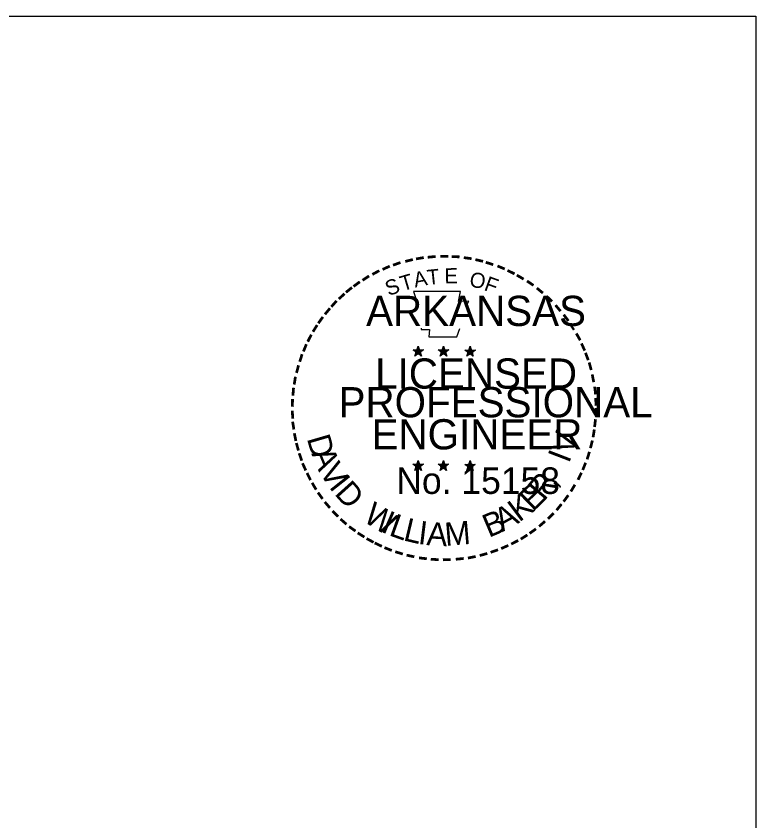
# Model space of a CAD drawing. Extents: x 28704 to 32542, y 50360 to 59122.
# Drawn here: x 30170 to 30422.7, y 58847.3 to 59122.4 of the extents above; entities that cross this region are included whole.
import ezdxf

# ---------------------------------------------------------------- set-up
doc = ezdxf.new("R2010")
doc.units = 0
doc.layers.add('R_Border Prem', color=7, linetype='Continuous')
doc.layers.add('R_Contours', color=7, linetype='Continuous')

msp = doc.modelspace()

# ---------------------------------------------------------------- linework, layer by layer
at = {"layer": 'R_Border Prem'}
for p, q in [((30305.59, 59008.27), (30307.38, 59007.7)), ((30305.59, 59008.27), (30306.89, 59008.04)), ((30305.59, 59008.27), (30306.81, 59007.64)), ((30307.38, 59009.58), (30307.17, 59008.28)), ((30307.38, 59007.7), (30307.38, 59009.58)), ((30307.38, 59009.58), (30307.64, 59008.29)), ((30309.17, 59008.27), (30307.38, 59007.7)), ((30309.17, 59008.27), (30307.7, 59008.02)), ((30309.17, 59008.27), (30308.12, 59007.74)), ((30314.2, 59008.27), (30316, 59007.7)), ((30314.2, 59008.27), (30315.5, 59008.04)), ((30314.2, 59008.27), (30315.42, 59007.64)), ((30316, 59009.58), (30315.78, 59008.28)), ((30316, 59007.7), (30316, 59009.58)), ((30316, 59009.58), (30316.25, 59008.29)), ((30317.79, 59008.27), (30316, 59007.7)), ((30317.79, 59008.27), (30316.31, 59008.02)), ((30317.79, 59008.27), (30316.73, 59007.74)), ((30323.29, 59008.21), (30325.09, 59007.63)), ((30323.29, 59008.21), (30324.6, 59007.97)), ((30323.29, 59008.21), (30324.51, 59007.58)), ((30325.09, 59009.52), (30324.88, 59008.22)), ((30325.09, 59007.63), (30325.09, 59009.52)), ((30325.09, 59009.52), (30325.34, 59008.23)), ((30326.88, 59008.21), (30325.09, 59007.63)), ((30326.88, 59008.21), (30325.41, 59007.95)), ((30326.88, 59008.21), (30325.83, 59007.68)), ((30306.27, 59006.16), (30307.38, 59007.7)), ((30306.27, 59006.16), (30306.92, 59007.42)), ((30306.27, 59006.16), (30307.37, 59007.28)), ((30308.48, 59006.16), (30307.37, 59007.27)), ((30308.48, 59006.16), (30307.38, 59007.7)), ((30308.48, 59006.16), (30307.78, 59007.66)), ((30314.88, 59006.16), (30316, 59007.7)), ((30314.88, 59006.16), (30315.53, 59007.42)), ((30314.88, 59006.16), (30315.99, 59007.28)), ((30317.09, 59006.16), (30315.99, 59007.27)), ((30317.09, 59006.16), (30316, 59007.7)), ((30317.09, 59006.16), (30316.39, 59007.66)), ((30323.98, 59006.1), (30325.09, 59007.63)), ((30323.98, 59006.1), (30324.63, 59007.36)), ((30323.98, 59006.1), (30325.08, 59007.22)), ((30326.19, 59006.1), (30325.08, 59007.21)), ((30326.19, 59006.1), (30325.09, 59007.63)), ((30326.19, 59006.1), (30325.48, 59007.6)), ((30307.36, 58970.53), (30307.15, 58969.23)), ((30307.36, 58968.65), (30307.36, 58970.53)), ((30307.36, 58970.53), (30307.62, 58969.24)), ((30315.97, 58970.53), (30315.76, 58969.23)), ((30315.97, 58968.65), (30315.97, 58970.53)), ((30315.97, 58970.53), (30316.22, 58969.24)), ((30325.08, 58970.48), (30324.87, 58969.18)), ((30325.08, 58968.6), (30325.08, 58970.48)), ((30325.08, 58970.48), (30325.33, 58969.19)), ((30305.56, 58969.22), (30307.36, 58968.65)), ((30305.56, 58969.22), (30306.87, 58968.99)), ((30305.56, 58969.22), (30306.79, 58968.59)), ((30306.25, 58967.12), (30307.36, 58968.65)), ((30306.25, 58967.12), (30306.9, 58968.37)), ((30306.25, 58967.12), (30307.35, 58968.24)), ((30308.46, 58967.12), (30307.35, 58968.22)), ((30309.15, 58969.22), (30307.36, 58968.65)), ((30308.46, 58967.12), (30307.36, 58968.65)), ((30309.15, 58969.22), (30307.68, 58968.97)), ((30308.46, 58967.12), (30307.76, 58968.62)), ((30309.15, 58969.22), (30308.1, 58968.69)), ((30314.17, 58969.22), (30315.97, 58968.65)), ((30314.17, 58969.22), (30315.48, 58968.99)), ((30314.17, 58969.22), (30315.39, 58968.59)), ((30314.86, 58967.12), (30315.97, 58968.65)), ((30314.86, 58967.12), (30315.51, 58968.37)), ((30314.86, 58967.12), (30315.96, 58968.24)), ((30317.07, 58967.12), (30315.96, 58968.22)), ((30317.76, 58969.22), (30315.97, 58968.65)), ((30317.07, 58967.12), (30315.97, 58968.65)), ((30317.76, 58969.22), (30316.28, 58968.97)), ((30317.07, 58967.12), (30316.36, 58968.62)), ((30317.76, 58969.22), (30316.71, 58968.69)), ((30323.28, 58969.17), (30325.08, 58968.6)), ((30323.28, 58969.17), (30324.59, 58968.94)), ((30323.28, 58969.17), (30324.5, 58968.54)), ((30323.97, 58967.06), (30325.08, 58968.6)), ((30323.97, 58967.06), (30324.62, 58968.32)), ((30323.97, 58967.06), (30325.07, 58968.18)), ((30326.18, 58967.06), (30325.07, 58968.17)), ((30326.87, 58969.17), (30325.08, 58968.6)), ((30326.18, 58967.06), (30325.08, 58968.6)), ((30326.87, 58969.17), (30325.4, 58968.92)), ((30326.18, 58967.06), (30325.47, 58968.57)), ((30326.87, 58969.17), (30325.82, 58968.64))]:
    msp.add_line(p, q, dxfattribs=at)
for points in [[(30305.8, 59028.26), (30307.18, 59024)], [(30323.9, 59023.51), (30324.63, 59024.97), (30321.1, 59024.85), (30321.86, 59028.26), (30305.8, 59028.26)], [(30308.33, 59015.77), (30308.33, 59015.32), (30311.24, 59015.22), (30310.96, 59012.79), (30320.6, 59012.79), (30321.64, 59015.55)], [(30307.38, 59009.58), (30308.48, 59006.16), (30305.59, 59008.27), (30309.17, 59008.27), (30306.27, 59006.16), (30307.38, 59009.58)], [(30316, 59009.58), (30317.09, 59006.16), (30314.2, 59008.27), (30317.79, 59008.27), (30314.88, 59006.16), (30316, 59009.58)], [(30325.09, 59009.52), (30326.19, 59006.1), (30323.29, 59008.21), (30326.88, 59008.21), (30323.98, 59006.1), (30325.09, 59009.52)], [(30307.36, 58970.53), (30308.46, 58967.12), (30305.56, 58969.22), (30309.15, 58969.22), (30306.25, 58967.12), (30307.36, 58970.53)], [(30315.97, 58970.53), (30317.07, 58967.12), (30314.17, 58969.22), (30317.76, 58969.22), (30314.86, 58967.12), (30315.97, 58970.53)], [(30325.08, 58970.48), (30326.18, 58967.06), (30323.28, 58969.17), (30326.87, 58969.17), (30323.97, 58967.06), (30325.08, 58970.48)]]:
    msp.add_lwpolyline(points, dxfattribs=at)
for centre, radius in [((30307.38, 59007.69), 0.888), ((30307.38, 59007.69), 0.745), ((30307.38, 59007.69), 0.597), ((30307.38, 59007.69), 0.511), ((30307.38, 59007.69), 0.385), ((30307.38, 59007.69), 0.255), ((30315.99, 59007.69), 0.888), ((30315.99, 59007.69), 0.745), ((30315.99, 59007.69), 0.597), ((30315.99, 59007.69), 0.511), ((30315.99, 59007.69), 0.385), ((30315.99, 59007.69), 0.255), ((30325.09, 59007.63), 0.888), ((30325.09, 59007.63), 0.745), ((30325.09, 59007.63), 0.597), ((30325.09, 59007.63), 0.511), ((30325.09, 59007.63), 0.385), ((30307.38, 59007.69), 0.153), ((30315.99, 59007.69), 0.153), ((30325.09, 59007.63), 0.255), ((30325.09, 59007.63), 0.153), ((30307.36, 58968.64), 0.888), ((30315.96, 58968.64), 0.888), ((30325.08, 58968.59), 0.888), ((30307.36, 58968.64), 0.745), ((30307.36, 58968.64), 0.597), ((30307.36, 58968.64), 0.511), ((30307.36, 58968.64), 0.385), ((30307.36, 58968.64), 0.255), ((30307.36, 58968.64), 0.153), ((30315.96, 58968.64), 0.745), ((30315.96, 58968.64), 0.597), ((30315.96, 58968.64), 0.511), ((30315.96, 58968.64), 0.385), ((30315.96, 58968.64), 0.255), ((30315.96, 58968.64), 0.153), ((30325.08, 58968.59), 0.745), ((30325.08, 58968.59), 0.597), ((30325.08, 58968.59), 0.511), ((30325.08, 58968.59), 0.385), ((30325.08, 58968.59), 0.255), ((30325.08, 58968.59), 0.153)]:
    msp.add_circle(centre, radius, dxfattribs=at)
at = {"layer": 'R_Contours'}
msp.add_line((28703.96, 59122.36), (30422.71, 59122.36), dxfattribs=at)
msp.add_lwpolyline([(28703.92, 59122.36), (30422.71, 59122.36), (30422.71, 58022.33), (28703.92, 58022.33)], close=True, dxfattribs=at)

# ---------------------------------------------------------------- texts
at = {"layer": 'R_Border Prem'}
for s, height, rotation, p in [('-', 8.25, 19.1761, (30299.34, 59034.08)), ('-', 8.25, 13.6302, (30303.21, 59035.32)), ('-', 8.25, 10.2193, (30306.7, 59036.15)), ('-', 8.25, 5.8968, (30310.46, 59036.72)), ('-', 8.25, 0.1862, (30314.44, 59037.09)), ('-', 8.25, 357.743, (30318.17, 59037.02)), ('-', 8.25, 352.1617, (30322.01, 59036.74)), ('-', 8.25, 347.2049, (30325.71, 59036.15)), ('-', 8.25, 342.3362, (30328.99, 59035.35)), ('-', 8.25, 28.7918, (30292.81, 59031.05)), ('-', 8.25, 24.3072, (30296.07, 59032.69)), ('T', 5.16, 6.0228, (30310.66, 59030.46)), ('E', 5.16, 0.8323, (30316.36, 59031.03)), ('-', 8.25, 337.8551, (30332.78, 59034.2)), ('-', 8.25, 334.1211, (30336.03, 59032.8)), ('-', 8.25, 34.0636, (30289.73, 59029.15)), ('T', 5.16, 16.4036, (30302.03, 59028.31)), ('A', 5.16, 11.2132, (30306.29, 59029.6)), ('O', 5.16, 350.4515, (30324.63, 59029.95)), ('F', 5.16, 340.0707, (30329.55, 59028.77)), ('-', 8.25, 329.6409, (30339.02, 59031.34)), ('-', 8.25, 38.9507, (30284.29, 59025.16)), ('-', 8.25, 36.2317, (30286.75, 59027.11)), ('S', 5.16, 21.594, (30297.31, 59026.6)), ('-', 8.25, 325.8627, (30342.33, 59029.48)), ('-', 8.25, 42.9622, (30282.06, 59023.01)), ('-', 8.25, 320.5297, (30345.48, 59027.28)), ('-', 8.25, 48.4231, (30279.75, 59020.55)), ('-', 8.25, 315.5786, (30348.57, 59024.77)), ('-', 8.25, 50.6142, (30277.67, 59018.04)), ('-', 8.25, 309.8797, (30351.5, 59021.93)), ('-', 8.25, 54.2325, (30275.54, 59015.12)), ('-', 8.25, 306.6522, (30354.21, 59018.83)), ('-', 8.25, 58.0706, (30273.87, 59012.4)), ('-', 7.22, 303.6753, (30356.71, 59015.9)), ('-', 8.25, 62.8713, (30272.25, 59009.23)), ('-', 8.25, 299.6684, (30358.36, 59012.77)), ('-', 8.25, 294.6628, (30360.03, 59009.61)), ('-', 8.25, 67.7743, (30270.92, 59006.08)), ('-', 8.25, 72.3945, (30269.79, 59002.83)), ('-', 8.25, 290.5728, (30361.35, 59006.64)), ('-', 8.25, 75.461, (30268.77, 58999.15)), ('-', 8.25, 285.1233, (30362.56, 59003.65)), ('-', 8.25, 280.5493, (30363.59, 58999.82)), ('-', 8.25, 81.2013, (30268.09, 58995.48)), ('-', 8.25, 85.1863, (30267.7, 58991.91)), ('-', 8.25, 276.5962, (30364.43, 58995.86)), ('-', 8.25, 89.0622, (30267.57, 58988.3)), ('-', 8.25, 274.3301, (30364.74, 58992.14)), ('-', 8.25, 94.1959, (30267.75, 58984.56)), ('-', 8.25, 269.9407, (30364.91, 58988.88)), ('-', 8.25, 98.9479, (30268.12, 58981.12)), ('-', 8.25, 263.5172, (30364.81, 58985.45)), ('V', 7.94, 72.6573, (30359.99, 58972.07)), ('-', 8.25, 260.9953, (30364.45, 58982.07)), ('-', 8.25, 101.7149, (30268.82, 58977.34)), ('D', 7.94, 286.2848, (30269.28, 58978.05)), ('-', 8.25, 105.4578, (30269.66, 58974.27)), ('-', 8.25, 255.7626, (30363.88, 58978.58)), ('-', 8.25, 109.0874, (30270.76, 58971.02)), ('A', 7.94, 292.7835, (30270.79, 58972.89)), ('I', 7.94, 69.0301, (30358.84, 58969.29)), ('-', 8.25, 252.8681, (30362.95, 58974.87)), ('-', 8.25, 114.0643, (30272.07, 58967.95)), ('V', 7.94, 300.7936, (30273.44, 58966.81)), ('-', 8.25, 247.8887, (30361.8, 58971.4)), ('-', 8.25, 115.7289, (30273.65, 58964.76)), ('I', 7.94, 308.3502, (30276.69, 58961.46)), ('R', 7.94, 50.3651, (30350.33, 58956.46)), ('-', 8.25, 244.6197, (30360.45, 58968.15)), ('-', 8.25, 120.4471, (30275.49, 58961.74)), ('D', 7.94, 311.9774, (30278.5, 58959.06)), ('E', 7.94, 44.0175, (30346.55, 58952.81)), (',', 7.94, 57.4684, (30354.06, 58961.01)), ('-', 8.25, 239.0712, (30358.42, 58964.28)), ('-', 8.25, 125.8934, (30277.57, 58958.85)), ('K', 7.94, 36.9143, (30341.86, 58949.25)), ('-', 8.25, 233.8452, (30356.34, 58960.91)), ('-', 8.25, 130.7181, (30279.95, 58956)), ('W', 7.94, 328.0731, (30288.18, 58949.95)), ('-', 8.25, 231.2538, (30354.13, 58957.99)), ('-', 8.25, 134.2238, (30282.61, 58953.19)), ('I', 7.94, 336.6877, (30294.31, 58946.29)), ('B', 7.94, 22.8589, (30331.48, 58944.04)), ('A', 7.94, 28.9042, (30336.1, 58945.97)), ('-', 8.25, 138.9338, (30285.32, 58950.8)), ('L', 7.94, 340.3149, (30297.04, 58945.04)), ('L', 7.94, 346.6625, (30301.98, 58943.26)), ('-', 8.25, 225.7653, (30351.66, 58955.08)), ('-', 8.25, 144.6463, (30288.19, 58948.7)), ('I', 7.94, 353.0101, (30307.1, 58942.04)), ('A', 7.94, 356.6373, (30310.07, 58941.6)), ('M', 7.94, 4.6473, (30316.7, 58941.3)), ('-', 8.25, 215.7363, (30346.13, 58950.02)), ('-', 8.25, 221.0851, (30348.96, 58952.46)), ('-', 8.25, 148.0898, (30291.08, 58946.79)), ('-', 8.25, 212.2491, (30343.38, 58948.03)), ('-', 8.25, 151.5704, (30294.07, 58945.11)), ('-', 8.25, 154.6002, (30296.76, 58943.84)), ('-', 8.25, 207.3568, (30340.5, 58946.24)), ('-', 8.25, 158.5612, (30299.97, 58942.53)), ('-', 8.25, 162.7983, (30303.52, 58941.43)), ('-', 8.25, 195.4743, (30330.6, 58941.94)), ('-', 8.25, 199.4643, (30334.03, 58943.17)), ('-', 8.25, 204.2516, (30337.28, 58944.6)), ('-', 8.25, 167.5555, (30307.2, 58940.59)), ('-', 8.25, 173.1155, (30311.18, 58940.02)), ('-', 8.25, 176.5183, (30315.04, 58939.75)), ('-', 8.25, 181.5918, (30318.88, 58939.84)), ('-', 8.25, 185.8167, (30323.05, 58940.24)), ('-', 8.25, 191.2858, (30326.84, 58940.92))]:
    msp.add_text(s, height=height, rotation=rotation, dxfattribs=at).set_placement(p)
for s, height, p in [('ARKANSAS', 10.312, (30289.57, 59016.47)), ('LICENSED', 10.312, (30292.65, 58995.07)), ('PROFESSIONAL', 10.3125, (30280.15, 58985.26)), ('ENGINEER', 10.312, (30291.43, 58974.3)), ('No. 15158', 9.06, (30299.89, 58959.08)), ('AAMU', 0.000103, (30315.63, 58941.27))]:
    msp.add_text(s, height=height, dxfattribs=at).set_placement(p)

doc.saveas('drawing.dxf')
